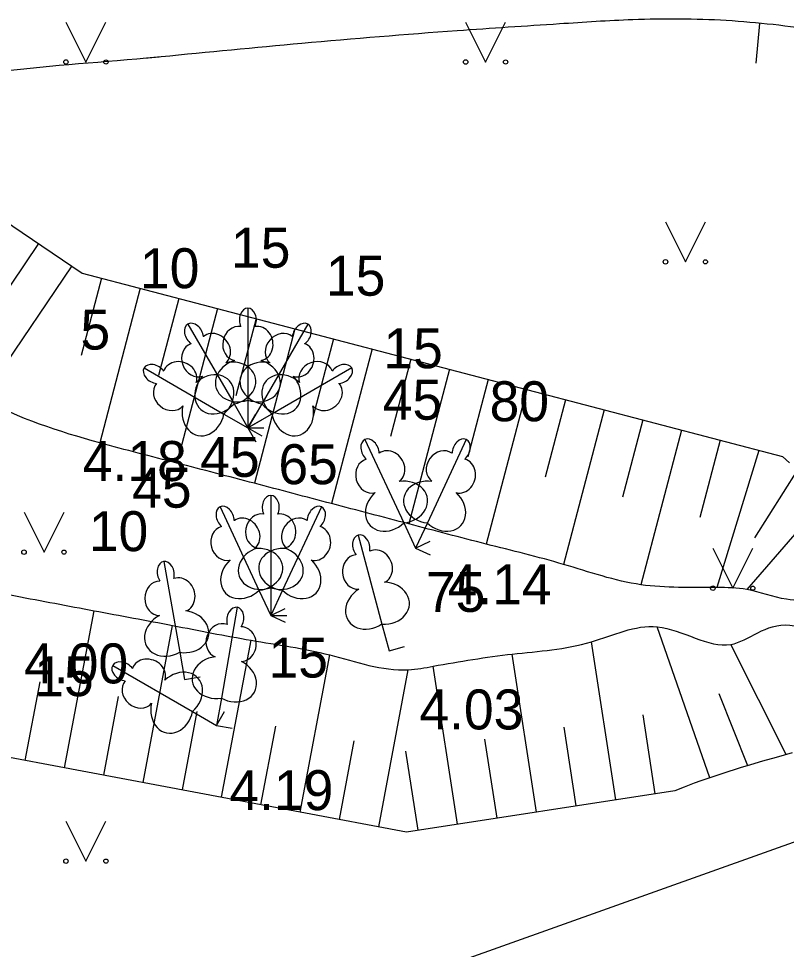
# Model space of a CAD drawing. Extents: x 519536 to 519949, y 326041 to 326519.
# Drawn here: x 519756.66 to 519766.26, y 326171.4 to 326183.04 of the extents above; entities that cross this region are included whole.
import ezdxf

# ---------------------------------------------------------------- set-up
doc = ezdxf.new("R2010")
doc.units = 0
for name, color, linetype in [('ELEK_VADP_ZSPR_####_#', 7, 'Continuous'), ('RELJ_AATZ_####_TKST_#', 7, 'Continuous'), ('RELJ_HORZ_PAMT_####_#', 7, 'Continuous'), ('RELJ_NOGA_####_####_#', 7, 'Continuous'), ('RELJ_NOGL_####_####_#', 7, 'Continuous'), ('TERT_DIAM_####_TKST_#', 7, 'Continuous'), ('TERT_ELEM_####_####_#', 7, 'Continuous')]:
    doc.layers.add(name, color=color, linetype=linetype)

msp = doc.modelspace()

# ---------------------------------------------------------------- linework, layer by layer
at = {"layer": 'ELEK_VADP_ZSPR_####_#'}
msp.add_lwpolyline([(519785.405, 326179.533), (519755.855, 326168.99), (519734.736, 326159.988)], dxfattribs=at)
at = {"layer": 'RELJ_HORZ_PAMT_####_#'}
msp.add_line((519765.927, 326182.984), (519765.88, 326182.487), dxfattribs=at)
for points in [[(519763.423, 326182.977), (519762.145, 326182.891), (519760.201, 326182.732), (519758.44, 326182.565)], [(519770.809, 326181.961), (519770.439, 326182.101), (519770.061, 326182.217), (519769.015, 326182.469), (519767.848, 326182.696), (519766.681, 326182.893), (519766.096, 326182.968), (519765.511, 326183.019), (519764.34, 326183.029), (519763.423, 326182.977)], [(519758.44, 326182.565), (519758.257, 326182.548), (519756.316, 326182.364), (519754.377, 326182.207), (519754.162, 326182.246), (519753.956, 326182.352), (519753.754, 326182.47), (519753.549, 326182.541), (519753.219, 326182.538), (519752.895, 326182.407), (519752.811, 326182.344), (519752.736, 326182.277), (519752.608, 326182.123), (519752.495, 326181.945)]]:
    msp.add_spline(points, degree=3, dxfattribs=at)
at = {"layer": 'RELJ_NOGA_####_####_#'}
for p, q in [((519756.908, 326180.229), (519756.348, 326179.4)), ((519757.323, 326179.949), (519756.203, 326178.292)), ((519757.454, 326179.86), (519766.215, 326177.562)), ((519757.454, 326179.86), (519766.215, 326177.562)), ((519757.454, 326179.86), (519766.215, 326177.562)), ((519757.454, 326179.86), (519766.215, 326177.562)), ((519757.454, 326179.86), (519766.215, 326177.562)), ((519757.454, 326179.86), (519766.215, 326177.562)), ((519757.454, 326179.86), (519766.215, 326177.562)), ((519757.454, 326179.86), (519766.215, 326177.562)), ((519757.454, 326179.86), (519766.215, 326177.562)), ((519757.454, 326179.86), (519766.215, 326177.562)), ((519757.454, 326179.86), (519766.215, 326177.562)), ((519757.454, 326179.86), (519766.215, 326177.562)), ((519757.696, 326179.797), (519757.442, 326178.829)), ((519758.179, 326179.67), (519757.672, 326177.735)), ((519758.663, 326179.543), (519758.409, 326178.576)), ((519759.147, 326179.416), (519758.639, 326177.481)), ((519759.63, 326179.289), (519759.377, 326178.322)), ((519760.114, 326179.162), (519759.607, 326177.228)), ((519760.598, 326179.035), (519760.344, 326178.068)), ((519761.081, 326178.909), (519760.574, 326176.974)), ((519761.565, 326178.782), (519761.311, 326177.814)), ((519762.049, 326178.655), (519761.541, 326176.72)), ((519762.532, 326178.528), (519762.278, 326177.561)), ((519763.016, 326178.401), (519762.508, 326176.467)), ((519763.499, 326178.274), (519763.246, 326177.307)), ((519763.983, 326178.147), (519763.476, 326176.213)), ((519764.467, 326178.021), (519764.213, 326177.053)), ((519764.95, 326177.894), (519764.443, 326175.959)), ((519765.434, 326177.767), (519765.18, 326176.8)), ((519765.918, 326177.64), (519765.393, 326175.925)), ((519766.403, 326177.397), (519765.862, 326176.544)), ((519766.795, 326177.088), (519765.768, 326175.898)), ((519757.232, 326173.668), (519757.602, 326175.634)), ((519758.215, 326173.484), (519758.585, 326175.449)), ((519765.304, 326173.543), (519764.648, 326175.432)), ((519759.198, 326173.299), (519759.567, 326175.264)), ((519764.127, 326173.266), (519763.823, 326175.243)), ((519766.26, 326173.834), (519765.567, 326175.211)), ((519760.181, 326173.114), (519760.55, 326175.08)), ((519763.138, 326173.114), (519762.834, 326175.091)), ((519762.15, 326172.962), (519761.846, 326174.939)), ((519761.164, 326172.929), (519761.533, 326174.895)), ((519756.741, 326173.761), (519756.926, 326174.743)), ((519765.78, 326173.694), (519765.42, 326174.592)), ((519757.724, 326173.576), (519757.908, 326174.559)), ((519758.707, 326173.391), (519758.891, 326174.374)), ((519764.621, 326173.342), (519764.469, 326174.33)), ((519759.689, 326173.206), (519759.874, 326174.189)), ((519763.633, 326173.19), (519763.481, 326174.178)), ((519760.672, 326173.022), (519760.857, 326174.004)), ((519762.644, 326173.038), (519762.492, 326174.027)), ((519761.656, 326172.886), (519761.504, 326173.875))]:
    msp.add_line(p, q, dxfattribs=at)
for points in [[(519756.078, 326180.79), (519757.454, 326179.86)], [(519756.078, 326180.79), (519757.454, 326179.86)], [(519756.078, 326180.79), (519757.454, 326179.86)], [(519756.078, 326180.79), (519757.454, 326179.86)], [(519756.078, 326180.79), (519757.454, 326179.86)], [(519756.078, 326180.79), (519757.454, 326179.86)], [(519756.078, 326180.79), (519757.454, 326179.86)], [(519756.078, 326180.79), (519757.454, 326179.86)], [(519756.078, 326180.79), (519757.454, 326179.86)], [(519756.078, 326180.79), (519757.454, 326179.86)], [(519756.078, 326180.79), (519757.454, 326179.86)], [(519756.078, 326180.79), (519757.454, 326179.86)], [(519766.215, 326177.562), (519766.302, 326177.484)], [(519766.215, 326177.562), (519766.302, 326177.484)], [(519766.215, 326177.562), (519766.302, 326177.484)], [(519766.215, 326177.562), (519766.302, 326177.484)], [(519766.215, 326177.562), (519766.302, 326177.484)], [(519766.215, 326177.562), (519766.302, 326177.484)], [(519766.215, 326177.562), (519766.302, 326177.484)], [(519766.215, 326177.562), (519766.302, 326177.484)], [(519766.215, 326177.562), (519766.302, 326177.484)], [(519766.215, 326177.562), (519766.302, 326177.484)], [(519766.215, 326177.562), (519766.302, 326177.484)], [(519766.215, 326177.562), (519766.302, 326177.484)], [(519764.868, 326173.38), (519761.511, 326172.864), (519752.196, 326174.615)], [(519764.868, 326173.38), (519761.511, 326172.864), (519752.196, 326174.615)], [(519764.868, 326173.38), (519761.511, 326172.864), (519752.196, 326174.615)], [(519764.868, 326173.38), (519761.511, 326172.864), (519752.196, 326174.615)], [(519764.868, 326173.38), (519761.511, 326172.864), (519752.196, 326174.615)], [(519764.868, 326173.38), (519761.511, 326172.864), (519752.196, 326174.615)], [(519764.868, 326173.38), (519761.511, 326172.864), (519752.196, 326174.615)], [(519764.868, 326173.38), (519761.511, 326172.864), (519752.196, 326174.615)], [(519764.868, 326173.38), (519761.511, 326172.864), (519752.196, 326174.615)], [(519764.868, 326173.38), (519761.511, 326172.864), (519752.196, 326174.615)], [(519764.868, 326173.38), (519761.511, 326172.864), (519752.196, 326174.615)], [(519764.868, 326173.38), (519761.511, 326172.864), (519752.196, 326174.615)], [(519766.335, 326173.855), (519766.136, 326173.798), (519765.963, 326173.749), (519765.814, 326173.705), (519765.686, 326173.666), (519765.466, 326173.597), (519765.307, 326173.544), (519765.192, 326173.504), (519765.108, 326173.474), (519764.985, 326173.427), (519764.868, 326173.38)], [(519766.335, 326173.855), (519766.136, 326173.798), (519765.963, 326173.749), (519765.814, 326173.705), (519765.686, 326173.666), (519765.466, 326173.597), (519765.307, 326173.544), (519765.192, 326173.504), (519765.108, 326173.474), (519764.985, 326173.427), (519764.868, 326173.38)], [(519766.335, 326173.855), (519766.136, 326173.798), (519765.963, 326173.749), (519765.814, 326173.705), (519765.686, 326173.666), (519765.466, 326173.597), (519765.307, 326173.544), (519765.192, 326173.504), (519765.108, 326173.474), (519764.985, 326173.427), (519764.868, 326173.38)], [(519766.335, 326173.855), (519766.136, 326173.798), (519765.963, 326173.749), (519765.814, 326173.705), (519765.686, 326173.666), (519765.466, 326173.597), (519765.307, 326173.544), (519765.192, 326173.504), (519765.108, 326173.474), (519764.985, 326173.427), (519764.868, 326173.38)], [(519766.335, 326173.855), (519766.136, 326173.798), (519765.963, 326173.749), (519765.814, 326173.705), (519765.686, 326173.666), (519765.466, 326173.597), (519765.307, 326173.544), (519765.192, 326173.504), (519765.108, 326173.474), (519764.985, 326173.427), (519764.868, 326173.38)], [(519766.335, 326173.855), (519766.136, 326173.798), (519765.963, 326173.749), (519765.814, 326173.705), (519765.686, 326173.666), (519765.466, 326173.597), (519765.307, 326173.544), (519765.192, 326173.504), (519765.108, 326173.474), (519764.985, 326173.427), (519764.868, 326173.38)], [(519766.335, 326173.855), (519766.136, 326173.798), (519765.963, 326173.749), (519765.814, 326173.705), (519765.686, 326173.666), (519765.466, 326173.597), (519765.307, 326173.544), (519765.192, 326173.504), (519765.108, 326173.474), (519764.985, 326173.427), (519764.868, 326173.38)], [(519766.335, 326173.855), (519766.136, 326173.798), (519765.963, 326173.749), (519765.814, 326173.705), (519765.686, 326173.666), (519765.466, 326173.597), (519765.307, 326173.544), (519765.192, 326173.504), (519765.108, 326173.474), (519764.985, 326173.427), (519764.868, 326173.38)], [(519766.335, 326173.855), (519766.136, 326173.798), (519765.963, 326173.749), (519765.814, 326173.705), (519765.686, 326173.666), (519765.466, 326173.597), (519765.307, 326173.544), (519765.192, 326173.504), (519765.108, 326173.474), (519764.985, 326173.427), (519764.868, 326173.38)], [(519766.335, 326173.855), (519766.136, 326173.798), (519765.963, 326173.749), (519765.814, 326173.705), (519765.686, 326173.666), (519765.466, 326173.597), (519765.307, 326173.544), (519765.192, 326173.504), (519765.108, 326173.474), (519764.985, 326173.427), (519764.868, 326173.38)], [(519766.335, 326173.855), (519766.136, 326173.798), (519765.963, 326173.749), (519765.814, 326173.705), (519765.686, 326173.666), (519765.466, 326173.597), (519765.307, 326173.544), (519765.192, 326173.504), (519765.108, 326173.474), (519764.985, 326173.427), (519764.868, 326173.38)], [(519766.335, 326173.855), (519766.136, 326173.798), (519765.963, 326173.749), (519765.814, 326173.705), (519765.686, 326173.666), (519765.466, 326173.597), (519765.307, 326173.544), (519765.192, 326173.504), (519765.108, 326173.474), (519764.985, 326173.427), (519764.868, 326173.38)]]:
    msp.add_lwpolyline(points, dxfattribs=at)
at = {"layer": 'RELJ_NOGL_####_####_#'}
msp.add_spline([(519750.737, 326177.254), (519750.215, 326177.377), (519749.969, 326177.484), (519750.048, 326177.953), (519750.261, 326178.326), (519750.676, 326178.661), (519751.369, 326179.175), (519752.072, 326179.621), (519752.69, 326179.926), (519753.234, 326180.089), (519753.479, 326180.102), (519753.717, 326179.972), (519754.546, 326179.412), (519755.374, 326178.852), (519756.203, 326178.292), (519757.672, 326177.735), (519758.639, 326177.481), (519759.607, 326177.228), (519760.574, 326176.974), (519761.541, 326176.72), (519762.508, 326176.467), (519763.476, 326176.213), (519764.443, 326175.959), (519765.393, 326175.925), (519765.768, 326175.898), (519766.265, 326175.777), (519766.935, 326175.588), (519767.042, 326175.305), (519766.305, 326175.453), (519765.567, 326175.211), (519764.648, 326175.432), (519763.823, 326175.243), (519762.834, 326175.091), (519761.846, 326174.939), (519761.533, 326174.895), (519760.55, 326175.08), (519759.567, 326175.264), (519758.585, 326175.449), (519757.602, 326175.634), (519756.619, 326175.819), (519755.636, 326176.003), (519754.653, 326176.188), (519753.671, 326176.373), (519752.688, 326176.558), (519752.282, 326176.749), (519751.361, 326177.138), (519750.737, 326177.254)], degree=3, dxfattribs=at)
at = {"layer": 'TERT_ELEM_####_####_#'}
for p, q in [((519757.25, 326183), (519757.5, 326182.5)), ((519757.5, 326182.5), (519757.75, 326183)), ((519762.25, 326183), (519762.5, 326182.5)), ((519762.5, 326182.5), (519762.75, 326183)), ((519764.75, 326180.5), (519765, 326180)), ((519765, 326180), (519765.25, 326180.5)), ((519759.353, 326178.223), (519759.526, 326177.922)), ((519759.526, 326178.269), (519759.526, 326177.922)), ((519759.699, 326178.223), (519759.526, 326177.922)), ((519759.225, 326178.095), (519759.526, 326177.922)), ((519759.526, 326177.922), (519759.626, 326178.095)), ((519759.827, 326178.095), (519759.526, 326177.922)), ((519759.526, 326177.922), (519759.699, 326178.022)), ((519759.526, 326177.922), (519759.726, 326177.922)), ((519759.526, 326177.922), (519759.626, 326177.749)), ((519759.526, 326177.922), (519759.699, 326177.822)), ((519756.726, 326176.867), (519756.976, 326176.367)), ((519756.976, 326176.367), (519757.226, 326176.867)), ((519761.477, 326176.732), (519761.624, 326176.418)), ((519761.771, 326176.732), (519761.624, 326176.418)), ((519761.624, 326176.418), (519761.805, 326176.503)), ((519761.624, 326176.418), (519761.805, 326176.333)), ((519765.343, 326176.415), (519765.593, 326175.915)), ((519765.593, 326175.915), (519765.843, 326176.415)), ((519759.665, 326175.889), (519759.812, 326175.575)), ((519759.812, 326175.922), (519759.812, 326175.575)), ((519759.959, 326175.889), (519759.812, 326175.575)), ((519759.812, 326175.575), (519759.993, 326175.66)), ((519759.812, 326175.575), (519760.012, 326175.575)), ((519759.812, 326175.575), (519759.993, 326175.49)), ((519761.203, 326175.467), (519761.293, 326175.132)), ((519761.293, 326175.132), (519761.486, 326175.184)), ((519758.673, 326175.114), (519758.733, 326174.772)), ((519758.733, 326174.772), (519758.93, 326174.807)), ((519759.194, 326174.541), (519759.134, 326174.199)), ((519758.833, 326174.372), (519759.134, 326174.199)), ((519759.134, 326174.199), (519759.234, 326174.372)), ((519759.134, 326174.199), (519759.331, 326174.164)), ((519757.25, 326173), (519757.5, 326172.5)), ((519757.5, 326172.5), (519757.75, 326173))]:
    msp.add_line(p, q, dxfattribs=at)
for points in [[(519759.526, 326179.422), (519759.526, 326178.269)], [(519758.776, 326179.221), (519759.353, 326178.223)], [(519759.616, 326179.19), (519759.615, 326179.191)], [(519760.276, 326179.221), (519759.699, 326178.223)], [(519758.97, 326179.065), (519758.968, 326179.065)], [(519760.237, 326178.975), (519760.237, 326178.976)], [(519758.227, 326178.672), (519759.225, 326178.095)], [(519760.825, 326178.672), (519759.827, 326178.095)], [(519758.473, 326178.633), (519758.472, 326178.633)], [(519760.669, 326178.478), (519760.669, 326178.48)], [(519760.99, 326177.777), (519761.477, 326176.732)], [(519762.258, 326177.777), (519761.771, 326176.732)], [(519761.169, 326177.605), (519761.168, 326177.605)], [(519762.241, 326177.529), (519762.24, 326177.53)], [(519759.812, 326177.075), (519759.812, 326175.922)], [(519759.178, 326176.934), (519759.665, 326175.889)], [(519760.446, 326176.934), (519759.959, 326175.889)], [(519759.902, 326176.843), (519759.901, 326176.844)], [(519759.357, 326176.762), (519759.356, 326176.762)], [(519760.429, 326176.686), (519760.428, 326176.687)], [(519760.905, 326176.581), (519761.203, 326175.467)], [(519761.051, 326176.38), (519761.05, 326176.38)], [(519758.473, 326176.249), (519758.673, 326175.114)], [(519758.601, 326176.036), (519758.6, 326176.037)], [(519759.394, 326175.676), (519759.194, 326174.541)], [(519759.442, 326175.432), (519759.441, 326175.433)], [(519757.835, 326174.949), (519758.833, 326174.372)], [(519758.081, 326174.91), (519758.08, 326174.91)]]:
    msp.add_lwpolyline(points, dxfattribs=at)
for centre, radius in [((519757.25, 326182.5), 0.028), ((519757.75, 326182.5), 0.0263), ((519762.25, 326182.5), 0.028), ((519762.75, 326182.5), 0.0263), ((519764.75, 326180), 0.028), ((519765.25, 326180), 0.0263), ((519756.725, 326176.367), 0.028), ((519757.225, 326176.367), 0.0263), ((519765.343, 326175.915), 0.028), ((519765.843, 326175.915), 0.0263), ((519757.25, 326172.5), 0.028), ((519757.75, 326172.5), 0.0263)]:
    msp.add_circle(centre, radius, dxfattribs=at)
for centre, major_axis, ratio, start_param, end_param in [((519759.526, 326179.272), (0, -0.15), 0.707107, 3.14537, 5.287485), ((519759.526, 326179.272), (0, -0.15), 0.707107, 0.995701, 3.137816), ((519758.851, 326179.091), (0.075, -0.13), 0.707107, 0.995701, 3.137816), ((519760.201, 326179.091), (-0.075, -0.13), 0.707107, 3.14537, 5.287485), ((519758.851, 326179.091), (0.075, -0.13), 0.707107, 3.14537, 5.287485), ((519759.11, 326178.9), (0.14, -0.165), 0.861323, 0, 3.141593), ((519759.398, 326178.977), (-0.039, -0.212), 0.861323, 3.141593, 6.283185), ((519759.654, 326178.977), (0.039, -0.212), 0.861323, 0, 3.141593), ((519759.942, 326178.9), (-0.14, -0.165), 0.861323, 3.141593, 6.283185), ((519760.201, 326179.091), (-0.075, -0.13), 0.707107, 0.995701, 3.137816), ((519758.887, 326178.772), (0.073, -0.203), 0.861323, 3.141593, 6.283185), ((519760.165, 326178.772), (-0.073, -0.203), 0.861323, 0, 3.141593), ((519758.676, 326178.561), (0.203, -0.073), 0.861323, 0, 3.141593), ((519759.436, 326178.515), (0.307, 0.095), 0.814445, 1.570796, 4.752015), ((519759.307, 326178.48), (-0.313, -0.071), 0.814445, 1.531171, 4.712389), ((519759.745, 326178.48), (0.313, -0.071), 0.814445, 1.570796, 4.752015), ((519759.616, 326178.515), (-0.307, 0.095), 0.814445, 1.531171, 4.712389), ((519760.376, 326178.561), (-0.203, -0.073), 0.861323, 3.141593, 6.283185), ((519758.357, 326178.597), (0.13, -0.075), 0.707107, 3.14537, 5.287485), ((519758.357, 326178.597), (0.13, -0.075), 0.707107, 0.995701, 3.137816), ((519760.695, 326178.597), (-0.13, -0.075), 0.707107, 3.14537, 5.287485), ((519760.695, 326178.597), (-0.13, -0.075), 0.707107, 0.995701, 3.137816), ((519759.152, 326178.391), (0.218, 0.236), 0.814445, 1.570796, 4.752015), ((519759.057, 326178.296), (-0.236, -0.218), 0.814445, 1.531171, 4.712389), ((519759.995, 326178.296), (0.236, -0.218), 0.814445, 1.570796, 4.752015), ((519759.9, 326178.391), (-0.218, 0.236), 0.814445, 1.531171, 4.712389), ((519758.548, 326178.338), (0.165, -0.14), 0.861323, 3.141593, 6.283185), ((519760.504, 326178.338), (-0.165, -0.14), 0.861323, 0, 3.141593), ((519758.968, 326178.141), (0.071, 0.313), 0.814445, 1.570796, 4.752015), ((519760.084, 326178.141), (-0.071, 0.313), 0.814445, 1.531171, 4.712389), ((519761.054, 326177.642), (0.063, -0.136), 0.707107, 3.14537, 5.287485), ((519761.053, 326177.641), (0.063, -0.136), 0.707107, 0.995701, 3.137816), ((519762.195, 326177.641), (-0.063, -0.136), 0.707107, 3.14537, 5.287485), ((519762.194, 326177.642), (-0.063, -0.136), 0.707107, 0.995701, 3.137816), ((519761.294, 326177.429), (0.125, -0.176), 0.861323, 0, 3.141593), ((519761.954, 326177.429), (-0.125, -0.176), 0.861323, 3.141593, 6.283185), ((519761.062, 326177.32), (0.055, -0.209), 0.861323, 3.141593, 6.283185), ((519762.186, 326177.32), (-0.055, -0.209), 0.861323, 0, 3.141593), ((519761.455, 326176.993), (-0.318, -0.043), 0.814445, 1.531171, 4.712389), ((519761.793, 326176.993), (0.318, -0.043), 0.814445, 1.570796, 4.752015), ((519759.812, 326176.925), (0, -0.15), 0.707107, 3.14537, 5.287485), ((519759.812, 326176.925), (0, -0.15), 0.707107, 0.995701, 3.137816), ((519761.292, 326176.918), (0.238, 0.216), 0.814445, 1.570796, 4.752015), ((519761.956, 326176.918), (-0.238, 0.216), 0.814445, 1.531171, 4.712389), ((519759.242, 326176.799), (0.063, -0.136), 0.707107, 3.14537, 5.287485), ((519759.241, 326176.798), (0.063, -0.136), 0.707107, 0.995701, 3.137816), ((519760.383, 326176.798), (-0.063, -0.136), 0.707107, 3.14537, 5.287485), ((519760.382, 326176.799), (-0.063, -0.136), 0.707107, 0.995701, 3.137816), ((519759.482, 326176.586), (0.125, -0.176), 0.861323, 0, 3.141593), ((519759.684, 326176.63), (-0.039, -0.212), 0.861323, 3.141593, 6.283185), ((519759.94, 326176.63), (0.039, -0.212), 0.861323, 0, 3.141593), ((519760.142, 326176.586), (-0.125, -0.176), 0.861323, 3.141593, 6.283185), ((519759.25, 326176.477), (0.055, -0.209), 0.861323, 3.141593, 6.283185), ((519760.374, 326176.477), (-0.055, -0.209), 0.861323, 0, 3.141593), ((519760.944, 326176.436), (0.039, -0.145), 0.707107, 3.14537, 5.287485), ((519760.943, 326176.436), (0.039, -0.145), 0.707107, 0.995701, 3.137816), ((519759.722, 326176.168), (0.307, 0.095), 0.814445, 1.570796, 4.752015), ((519759.643, 326176.15), (-0.318, -0.043), 0.814445, 1.531171, 4.712389), ((519759.981, 326176.15), (0.318, -0.043), 0.814445, 1.570796, 4.752015), ((519759.902, 326176.168), (-0.307, 0.095), 0.814445, 1.531171, 4.712389), ((519760.896, 326176.118), (0.018, -0.215), 0.861323, 3.141593, 6.283185), ((519761.144, 326176.184), (0.092, -0.195), 0.861323, 6.283185, 9.424778), ((519758.499, 326176.102), (0.026, -0.148), 0.707107, 3.14537, 5.287485), ((519758.498, 326176.101), (0.026, -0.148), 0.707107, 0.995701, 3.137816), ((519759.48, 326176.075), (0.238, 0.216), 0.814445, 1.570796, 4.752015), ((519760.144, 326176.075), (-0.238, 0.216), 0.814445, 1.531171, 4.712389), ((519758.423, 326175.789), (-0.001, -0.216), 0.861323, 3.141593, 6.283185), ((519758.676, 326175.833), (0.075, -0.202), 0.861323, 0, 3.141593), ((519761.226, 326175.728), (-0.321, 0.012), 0.814445, 1.531171, 4.712389), ((519761.053, 326175.682), (0.272, 0.171), 0.814445, 1.570796, 4.752015), ((519758.718, 326175.371), (-0.319, 0.04), 0.814445, 1.531171, 4.712389), ((519759.369, 326175.528), (-0.026, -0.148), 0.707107, 3.14537, 5.287485), ((519759.368, 326175.529), (-0.026, -0.148), 0.707107, 0.995701, 3.137816), ((519758.542, 326175.34), (0.286, 0.147), 0.814445, 1.570796, 4.752015), ((519759.191, 326175.26), (-0.075, -0.202), 0.861323, 3.141593, 6.283185), ((519759.444, 326175.216), (0.001, -0.216), 0.861323, 0, 3.141593), ((519758.284, 326174.838), (0.203, -0.073), 0.861323, 0, 3.141593), ((519759.149, 326174.798), (0.319, 0.04), 0.814445, 1.570796, 4.752015), ((519757.965, 326174.874), (0.13, -0.075), 0.707107, 3.14537, 5.287485), ((519757.965, 326174.874), (0.13, -0.075), 0.707107, 0.995701, 3.137816), ((519759.325, 326174.767), (-0.286, 0.147), 0.814445, 1.531171, 4.712389), ((519758.665, 326174.573), (-0.236, -0.218), 0.814445, 1.531171, 4.712389), ((519758.156, 326174.615), (0.165, -0.14), 0.861323, 3.141593, 6.283185), ((519758.576, 326174.418), (0.071, 0.313), 0.814445, 1.570796, 4.752015)]:
    msp.add_ellipse(centre, major_axis=major_axis, ratio=ratio, start_param=start_param, end_param=end_param, dxfattribs=at)

# ---------------------------------------------------------------- texts
at = {"layer": 'RELJ_AATZ_####_TKST_#'}
for s, p in [('4.18', (519757.461, 326177.257)), ('4.14', (519762.025, 326175.714)), ('4.00', (519756.727, 326174.724)), ('4.03', (519761.671, 326174.148)), ('4.19', (519759.294, 326173.138))]:
    msp.add_text(s, height=0.5, dxfattribs=at).set_placement(p)
at = {"layer": 'TERT_DIAM_####_TKST_#'}
for s, p in [('15', (519759.315, 326179.926)), ('10', (519758.176, 326179.67)), ('15', (519760.502, 326179.576)), ('5', (519757.432, 326178.902)), ('15', (519761.221, 326178.668)), ('45', (519761.213, 326178.024)), (' 80', (519762.364, 326178.005)), ('45', (519758.93, 326177.309)), ('65', (519759.908, 326177.217)), ('45', (519758.078, 326176.923)), ('10', (519757.536, 326176.379)), ('75', (519761.753, 326175.619)), ('15', (519759.784, 326174.797)), ('15', (519756.854, 326174.564))]:
    msp.add_text(s, height=0.5, dxfattribs=at).set_placement(p)

doc.saveas('drawing.dxf')
